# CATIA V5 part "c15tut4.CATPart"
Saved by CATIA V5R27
Part number: Part1
Bounding box of the stored display mesh (mm): x -3 to 154, y -3 to 154, z -47 to 3.015
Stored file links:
  E:\_Deepak\2017_Deepak\CATIA\Resources\Tutorial Files\Tutorials\c15_catia_v5_6r2016_tut\c15tut4.CATPart
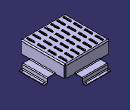
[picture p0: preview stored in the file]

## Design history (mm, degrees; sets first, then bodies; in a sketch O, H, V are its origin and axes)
SheetMetalParameters1: Thickness 1, BendRadius 2, KFactor 0.400515 {= log(min(100,max(20*SheetMetalParameters1.BendRadius,SheetMetalParameters1.Thickness)/SheetMetalParameters1.Thickness))/log(100)/2}, ReliefRadialLength 1, ReliefAxialLength 2, MinimumBendRadius 0
Body1 (main body)
  Sketch1 on xy-plane, origin (0, 0, 0), H (1, 0, 0), V (0, 1, 0)
    line L1 (0, 0) -> (120, 0)
    line L2 (120, 0) -> (120, 120)
    line L3 (120, 120) -> (0, 120)
    line L4 (0, 120) -> (0, 0)
    length L3 = 120
    length L2 = 120
    horizontal: L1 H, L3 H
    vertical: L2 V, L4 V
  Wall1: Thickness 1, Profile Sketch1
  Flange1: Angle 90, Length 34, Radius 2, KFacteur 0.400515 {= log(min(100,max(20*Flange1.Radius,SheetMetalParameters1.Thickness)/SheetMetalParameters1.Thickness))/log(100)/2}, Guide edge [face of Wall1 | face of Wall1]
  Flange2: Angle 90, Length 34, Radius 2, KFacteur 0.400515 {= log(min(100,max(20*Flange2.Radius,SheetMetalParameters1.Thickness)/SheetMetalParameters1.Thickness))/log(100)/2}, Guide edge [face of Wall1 | face of Wall1]
  Flange3: Angle 90, Length 34, Radius 2, KFacteur 0.400515 {= log(min(100,max(20*Flange3.Radius,SheetMetalParameters1.Thickness)/SheetMetalParameters1.Thickness))/log(100)/2}, Guide edge [face of Wall1 | face of Wall1]
  Flange4: Angle 90, Length 34, Radius 2, KFacteur 0.400515 {= log(min(100,max(20*Flange4.Radius,SheetMetalParameters1.Thickness)/SheetMetalParameters1.Thickness))/log(100)/2}, Guide edge [face of Wall1 | face of Wall1]
  d_NewWallOnEdge1: NewWallOnEdge_Edge edge [face of Flange3 | face of Flange3], NewWallOnEdge_Length 21, NewWallOnEdge_HeightLimitOffset 0, NewWallOnEdge_WidthOffset1 -25, NewWallOnEdge_WidthOffset2 -25, NewWallOnEdge_Angle 90, NewWallOnEdge_BendRadiusValue 2 {= SheetMetalParameters1.BendRadius}, NewWallOnEdge_BendTable SheetMetalParameters1, KFacteur 0.400515 {= log(min(100,max(20*d_NewWallOnEdge1.Radius,SheetMetalParameters1.Thickness)/SheetMetalParameters1.Thickness))/log(100)/2}
  Flange5: Angle 90, Length 13, Radius 1, KFacteur 0.325257 {= log(min(100,max(20*Flange5.Radius,SheetMetalParameters1.Thickness)/SheetMetalParameters1.Thickness))/log(100)/2}, Guide edge [face of d_NewWallOnEdge1 | face of d_NewWallOnEdge1]
  d_NewWallOnEdge2: NewWallOnEdge_Edge edge [face of Flange5 | face of Flange5], NewWallOnEdge_Length 10, NewWallOnEdge_HeightLimitOffset 0, NewWallOnEdge_WidthOffset1 0, NewWallOnEdge_WidthOffset2 0, NewWallOnEdge_Angle 90, NewWallOnEdge_BendRadiusValue 2 {= SheetMetalParameters1.BendRadius}, NewWallOnEdge_BendTable SheetMetalParameters1, KFacteur 0.400515 {= log(min(100,max(20*d_NewWallOnEdge2.Radius,SheetMetalParameters1.Thickness)/SheetMetalParameters1.Thickness))/log(100)/2}
  d_NewWallOnEdge3: NewWallOnEdge_Edge edge [face of Flange2 | face of Flange2], NewWallOnEdge_Length 21, NewWallOnEdge_HeightLimitOffset 0, NewWallOnEdge_WidthOffset1 -25, NewWallOnEdge_WidthOffset2 -25, NewWallOnEdge_Angle 90, NewWallOnEdge_BendRadiusValue 2 {= SheetMetalParameters1.BendRadius}, NewWallOnEdge_BendTable SheetMetalParameters1, KFacteur 0.400515 {= log(min(100,max(20*d_NewWallOnEdge3.Radius,SheetMetalParameters1.Thickness)/SheetMetalParameters1.Thickness))/log(100)/2}
  Flange6: Angle 90, Length 13, Radius 1, KFacteur 0.325257 {= log(min(100,max(20*Flange6.Radius,SheetMetalParameters1.Thickness)/SheetMetalParameters1.Thickness))/log(100)/2}, Guide edge [face of d_NewWallOnEdge3 | face of d_NewWallOnEdge3]
  d_NewWallOnEdge4: NewWallOnEdge_Edge edge [face of Flange6 | face of Flange6], NewWallOnEdge_Length 10, NewWallOnEdge_HeightLimitOffset 0, NewWallOnEdge_WidthOffset1 0, NewWallOnEdge_WidthOffset2 0, NewWallOnEdge_Angle 90, NewWallOnEdge_BendRadiusValue 2 {= SheetMetalParameters1.BendRadius}, NewWallOnEdge_BendTable SheetMetalParameters1, KFacteur 0.400515 {= log(min(100,max(20*d_NewWallOnEdge4.Radius,SheetMetalParameters1.Thickness)/SheetMetalParameters1.Thickness))/log(100)/2}
  Sketch2 on face of d_NewWallOnEdge2, origin (31.3691, 147.6369, -46), H (1, 0, 0), V (0, 1, 0)
    point P1 (-1.3691, 2.3631)
    reference projected line E1 (-6.3691, 6.3631) -> (63.6309, 6.3631) from edge [face of d_NewWallOnEdge2 | face of d_NewWallOnEdge2]
    reference projected line E2 (-6.3691, -0.6369) -> (-6.3691, 6.3631) from edge [face of d_NewWallOnEdge2 | face of d_NewWallOnEdge2]
    distance P1 E1 = 4
    distance P1 E2 = 5
  Hole1: placed by Sketch2, at (30, 150, -46) direction (0, 0, -1), diameter 3, through (limit type 6)
  Sketch3 on face of d_NewWallOnEdge2, origin (79.2942, 150.7856, -46), H (1, 0, 0), V (0, 1, 0)
    point P1 (10.7058, -0.7856)
    reference projected line E1 (-54.2942, 3.2144) -> (15.7058, 3.2144) from edge [face of d_NewWallOnEdge2 | face of d_NewWallOnEdge2]
    reference projected line E2 (15.7058, 3.2144) -> (15.7058, -3.7856) from edge [face of d_NewWallOnEdge2 | face of d_NewWallOnEdge2]
    distance P1 E1 = 4
    distance P1 E2 = 5
  Hole2: placed by Sketch3, at (90, 150, -46) direction (0, 0, -1), diameter 3, through (limit type 6)
  Sketch4 on face of d_NewWallOnEdge4, origin (148.0642, 84.3582, -46), H (1, 0, 0), V (0, 1, 0)
    point P1 (1.9358, 5.6418)
    reference projected line E1 (5.9358, 10.6418) -> (5.9358, -59.3582) from edge [face of d_NewWallOnEdge4 | face of d_NewWallOnEdge4]
    reference projected line E2 (-1.0642, 10.6418) -> (5.9358, 10.6418) from edge [face of d_NewWallOnEdge4 | face of d_NewWallOnEdge4]
    distance P1 E1 = 4
    distance P1 E2 = 5
  Hole3: placed by Sketch4, at (150, 90, -46) direction (0, 0, -1), diameter 3, through (limit type 6)
  Sketch5 on face of d_NewWallOnEdge4, origin (149.1042, 61.7681, -46), H (1, 0, 0), V (0, 1, 0)
    point P1 (0.8958, -31.7681)
    reference projected line E1 (4.8958, -36.7681) -> (-2.1042, -36.7681) from edge [face of d_NewWallOnEdge4 | face of d_NewWallOnEdge4]
    reference projected line E2 (4.8958, 33.2319) -> (4.8958, -36.7681) from edge [face of d_NewWallOnEdge4 | face of d_NewWallOnEdge4]
    distance E1 P1 = 5
    distance P1 E2 = 4
  Hole4: placed by Sketch5, at (150, 30, -46) direction (0, 0, -1), diameter 3, through (limit type 6)
  Sketch6 on face of Wall1, origin (0, 0, 0), H (1, 0, 0), V (0, -1, 0)
    line L1 (112, -115) -> (109.5, -115)
    line L2 (109.5, -115) -> (109.5, -95)
    line L3 (109.5, -95) -> (112, -95)
    line L4 (112, -95) -> (112, -115)
    reference projected line E1 (0, -123) -> (120, -123) from edge [face of Flange3 | face of Flange3]
    reference projected line E2 (123, -120) -> (123, 0) from edge [face of Flange2 | face of Flange2]
    distance L2 L4 = 2.5
    length L2 = 20
    distance L1 E1 = 8
    distance L4 E2 = 11
    horizontal: L1 H, L3 H
    vertical: L2 V, L4 V
  d_Stamp1: NewRoot_AttribNormalisation "No Standard", Stamp_FilletRadius 0.25
  RectPattern1: of d_Stamp1, direction 1 instances 7, spacing 17, along edge [face of Flange3 | face of Flange3] reversed, direction 2 instances 4, spacing 30, along edge [face of Flange2 | face of Flange2]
